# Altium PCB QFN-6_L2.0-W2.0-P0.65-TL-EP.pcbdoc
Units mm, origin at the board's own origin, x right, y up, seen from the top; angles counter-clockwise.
Board outline 15.76 x 14.85 mm, 2 copper layers (Top Layer, Bottom Layer), stack 0 mm thick; 1 components, 0 nets, 7 pads, 0 vias.
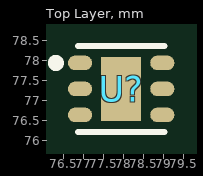
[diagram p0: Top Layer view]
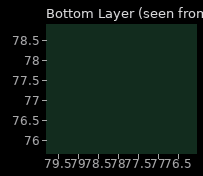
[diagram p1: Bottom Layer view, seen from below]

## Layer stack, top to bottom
Top Layer: signal copper (thickness not stored)
Bottom Layer: signal copper (thickness not stored)

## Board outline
85.614,69.85 69.85,69.85 69.85,84.702 85.614,84.702

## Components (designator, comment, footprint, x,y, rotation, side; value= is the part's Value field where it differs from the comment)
U? "" QFN-6_L2.0-W2.0-P0.65-TL-EP 77.932,77.276 r0 top

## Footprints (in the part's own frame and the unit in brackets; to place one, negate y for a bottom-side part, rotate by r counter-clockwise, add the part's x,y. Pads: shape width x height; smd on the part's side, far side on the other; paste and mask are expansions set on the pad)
QFN-6_L2.0-W2.0-P0.65-TL-EP [mm]
  oval 0.607x0.364 smd: 1(-1.028,0.65) 2(-1.028,0) 3(-1.028,-0.65) 4(1.028,-0.65) 5(1.028,0) 6(1.028,0.65)
  rect 1x1.6 smd: 7(0,0)
  silkscreen extent -1.73,-1.08 1.08,1.08

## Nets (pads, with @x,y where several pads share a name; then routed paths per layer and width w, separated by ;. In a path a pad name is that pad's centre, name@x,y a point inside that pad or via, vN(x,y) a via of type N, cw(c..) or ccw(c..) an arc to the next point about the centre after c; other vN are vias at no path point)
pads on no net: U?.1 U?.2 U?.3 U?.4 U?.5 U?.6 U?.7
